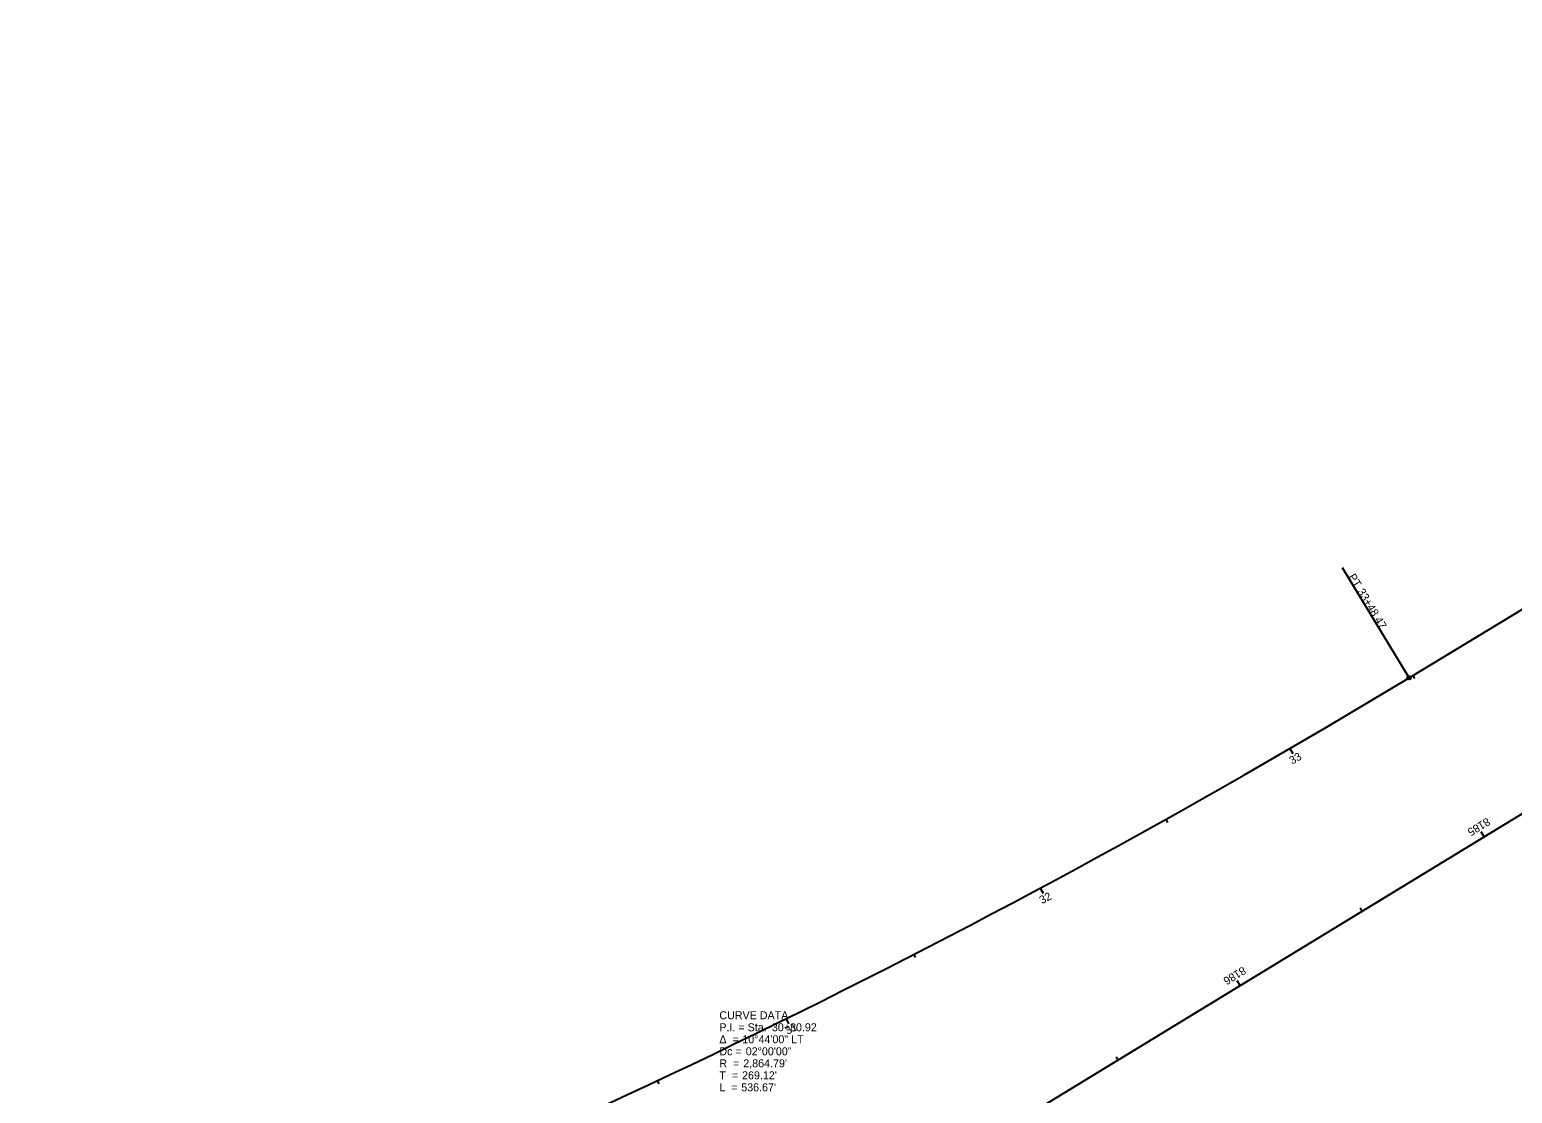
# Model space of a CAD drawing. Extents: x 2047945 to 2050534, y 355635 to 356996.
# Drawn here: x 2048721 to 2049240, y 356011 to 356383 of the extents above; entities that cross this region are included whole.
import ezdxf

# ---------------------------------------------------------------- set-up
doc = ezdxf.new("R2010")
doc.units = 0
for name, color, linetype in [('GE_X_Alignment_100_Cardinal_Points', 7, 'Continuous'), ('GE_X_Alignment_100_Curve_Data', 7, 'Continuous'), ('GE_X_Alignment_100_Stations', 7, 'Continuous'), ('RW_X_CL', 7, 'Continuous')]:
    doc.layers.add(name, color=color, linetype=linetype)

msp = doc.modelspace()

# ---------------------------------------------------------------- linework, layer by layer
at = {"layer": 'GE_X_Alignment_100_Cardinal_Points'}
msp.add_line((2049203.63, 356156.68), (2049180.35, 356195.19), dxfattribs=at)
msp.add_circle((2049203.63, 356156.68), 0.6, dxfattribs=at)
at = {"layer": 'GE_X_Alignment_100_Stations'}
for p, q in [((2049204.95, 356157.48), (2049205.57, 356156.45)), ((2049161.95, 356131.96), (2049162.95, 356130.23)), ((2049118.51, 356107.19), (2049119.1, 356106.15)), ((2049229.91, 356101.11), (2049228.87, 356102.82)), ((2049074.65, 356083.19), (2049075.6, 356081.43)), ((2049187.22, 356075.09), (2049186.59, 356076.11)), ((2049030.38, 356059.96), (2049030.93, 356058.89)), ((2049144.52, 356049.06), (2049143.48, 356050.77)), ((2048985.71, 356037.5), (2048986.59, 356035.7)), ((2049101.83, 356023.03), (2049101.21, 356024.06)), ((2048940.65, 356015.82), (2048941.16, 356014.74))]:
    msp.add_line(p, q, dxfattribs=at)
at = {"layer": 'RW_X_CL'}
for p, q in [((2050510.68, 356881.9), (2048727.85, 355795.04)), ((2049203.63, 356156.68), (2049557.91, 356370.89))]:
    msp.add_line(p, q, dxfattribs=at)
msp.add_arc((2047721.35, 358608.18), 2864.79, 290.42564, 301.15897, dxfattribs=at)

# ---------------------------------------------------------------- texts
at = {"layer": 'GE_X_Alignment_100_Cardinal_Points'}
for s, p in [('PT', (2049182.29, 356192.07)), ('33+48.47', (2049185.44, 356186.87))]:
    msp.add_text(s, height=2.8, rotation=301.159, dxfattribs=at).set_placement(p)
at = {"layer": 'GE_X_Alignment_100_Curve_Data'}
for s, p in [('CURVE DATA', (2048962.39, 356037.3)), ('Δ  = ', (2048962.39, 356028.9)), ('P.I. = Sta. ', (2048962.39, 356033.1)), ('10°44\'00" LT', (2048970.41, 356028.9)), ('30+80.92', (2048980.75, 356033.1)), ('Dc = ', (2048962.39, 356024.7)), ('02°00\'00"', (2048971.62, 356024.7)), ('R  = ', (2048962.39, 356020.5)), ("2,864.79'", (2048970.75, 356020.5)), ('T  = ', (2048962.39, 356016.3)), ("269.12'", (2048970.32, 356016.3)), ('L  = ', (2048962.39, 356012.1)), ("536.67'", (2048970.03, 356012.1))]:
    msp.add_text(s, height=2.8, dxfattribs=at).set_placement(p)
at = {"layer": 'GE_X_Alignment_100_Stations'}
for s, rotation, p in [('33', 30.1896, (2049162.73, 356126.28)), ('8185', 211.3674, (2049230.89, 356107.92)), ('32', 28.1896, (2049075.23, 356077.49)), ('8186', 211.3674, (2049145.5, 356055.86)), ('31', 26.1896, (2048986.23, 356031.85))]:
    msp.add_text(s, height=2.8, rotation=rotation, dxfattribs=at).set_placement(p)

doc.saveas('drawing.dxf')
